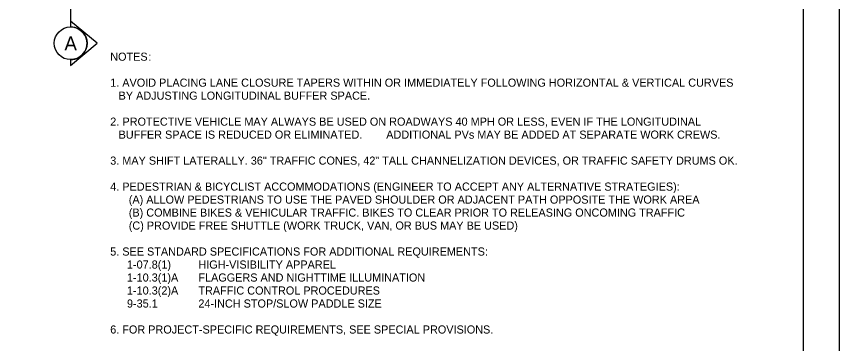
# Model space of a CAD drawing. Extents: x 99999.1 to 100095.7, y 99995 to 100010.7.
# Drawn here: x 100008.97 to 100016.06, y 100002.79 to 100005.61 of the extents above; entities that cross this region are included whole.
import ezdxf

# ---------------------------------------------------------------- set-up
doc = ezdxf.new("R2010")
doc.units = 0
for name, color, linetype in [('SH_GI_GeneralNotesBodyText', 7, 'Continuous'), ('SH_GI_PlotLimits', 7, 'Continuous'), ('SH_GI_SheetBorder', 7, 'Continuous'), ('SH_TI_WZSectionCut', 7, 'Continuous')]:
    doc.layers.add(name, color=color, linetype=linetype)

msp = doc.modelspace()

# ---------------------------------------------------------------- linework, layer by layer
at = {"layer": 'SH_GI_PlotLimits'}
msp.add_lwpolyline([(99999.0625, 99999.6875), (100016.0625, 99999.6875), (100016.0625, 100010.6875), (99999.0625, 100010.6875)], close=True, dxfattribs=at)
at = {"layer": 'SH_GI_SheetBorder'}
msp.add_line((100015.75, 100010.375), (100015.75, 100000), dxfattribs=at)
at = {"layer": 'SH_TI_WZSectionCut'}
for p, q in [((100009.4338, 100007.7022), (100009.4338, 100005.5723)), ((100009.4337, 100005.5723), (100009.4337, 100005.5224)), ((100009.6619, 100005.3812), (100009.4337, 100005.5723)), ((100009.4337, 100005.1901), (100009.6619, 100005.3812)), ((100009.4337, 100005.24), (100009.4337, 100005.1901))]:
    msp.add_line(p, q, dxfattribs=at)
msp.add_circle((100009.4338, 100005.3812), 0.1412, dxfattribs=at)
msp.add_arc((100009.4338, 100005.3812), 0.1412, 269.99779, 90.00221, dxfattribs=at)

# ---------------------------------------------------------------- texts
at = {"layer": 'SH_GI_GeneralNotesBodyText'}
for s, p in [('NOTES', (100009.7751, 100005.2306)), (':', (100010.1026, 100005.2306)), ('1. AVOID PLACING LANE CLOSURE TAPERS WITHIN OR IMMEDIATELY FOLLOWING HORIZONTAL & VERTICAL CURVES ', (100009.7751, 100005.0066)), ('BY ADJUSTING LONGITUDINAL BUFFER SPACE.', (100009.8473, 100004.8946)), ('2. ', (100009.7751, 100004.6706)), ('PROTECTIVE VEHICLE MAY ALWAYS BE USED ON ROADWAYS 40 MPH OR LESS, EVEN IF THE LONGITUDINAL ', (100009.8808, 100004.6706)), ('BUFFER SPACE IS REDUCED OR ELIMINATED.', (100009.8473, 100004.5586)), ('  ADDITIONAL PVs MAY BE ADDED AT SEPARATE WORK CREWS.', (100012.1026, 100004.5586)), ('3. MAY SHIFT LATERALLY. 36" TRAFFIC CONES, 42" TALL CHANNELIZATION DEVICES, OR TRAFFIC SAFETY DRUMS OK.', (100009.7751, 100004.3346)), ('4. PEDESTRIAN & BICYCLIST ACCOMMODATIONS (ENGINEER TO ACCEPT ANY ALTERNATIVE STRATEGIES):', (100009.7751, 100004.1106)), ('(A) ALLOW PEDESTRIANS TO USE THE PAVED SHOULDER OR ADJACENT PATH OPPOSITE THE WORK AREA', (100009.9351, 100003.9986)), ('(B) COMBINE BIKES & VEHICULAR TRAFFIC. BIKES TO CLEAR PRIOR TO RELEASING ONCOMING TRAFFIC', (100009.9351, 100003.8866)), ('(C) PROVIDE FREE SHUTTLE (WORK TRUCK, VAN, OR BUS MAY BE USED)', (100009.9351, 100003.7746)), ('5. SEE STANDARD SPECIFICATIONS FOR ADDITIONAL REQUIREMENTS:', (100009.7751, 100003.5506)), ('1-07.8(1) ', (100009.9195, 100003.4386)), ('HIGH-VISIBILITY APPAREL', (100010.5351, 100003.4386)), ('1-10.3(1)A ', (100009.9195, 100003.3266)), ('FLAGGERS AND NIGHTTIME ILLUMINATION', (100010.5351, 100003.3266)), ('1-10.3(2)A', (100009.9195, 100003.2146)), ('TRAFFIC CONTROL PROCEDURES', (100010.5351, 100003.2146)), ('9-35.1', (100009.9195, 100003.1026)), ('24-INCH STOP/SLOW PADDLE SIZE', (100010.5351, 100003.1026)), ('6. FOR PROJECT-SPECIFIC REQUIREMENTS, SEE SPECIAL PROVISIONS.', (100009.7751, 100002.8786))]:
    msp.add_text(s, height=0.07, rotation=360, dxfattribs=at).set_placement(p)
at = {"layer": 'SH_TI_WZSectionCut'}
msp.add_text('A', height=0.12, rotation=0.00995, dxfattribs=at).set_placement((100009.3808, 100005.3203))

doc.saveas('drawing.dxf')
